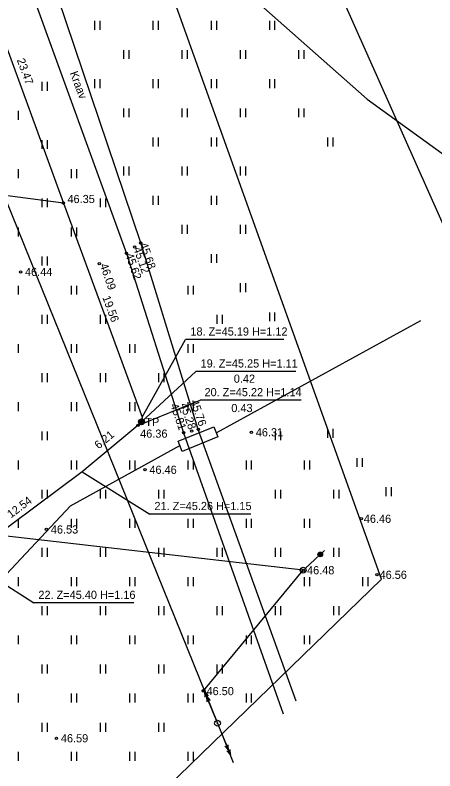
# Model space of a CAD drawing. Extents: x 642747 to 644424, y 6457048 to 6458238.
# Drawn here: x 644107 to 644143, y 6457581.9 to 6457646.8 of the extents above; entities that cross this region are included whole.
import ezdxf

# ---------------------------------------------------------------- set-up
doc = ezdxf.new("R2010")
doc.units = 0
for name, color, linetype in [('HALJASTUS', 7, 'Continuous'), ('JOONSIDE', 7, 'Continuous'), ('KOORDPUNKT', 7, 'Continuous'), ('KORGUS', 7, 'Continuous'), ('KPKAABEL', 7, 'Continuous'), ('KPOHULIIN', 7, 'Continuous'), ('MOOTPIIR', 7, 'Continuous'), ('PIIR', 7, 'Continuous'), ('POST', 7, 'Continuous'), ('RAJATIS', 7, 'Continuous'), ('SIOHULIIN', 7, 'Continuous'), ('SITRASS', 7, 'Continuous'), ('TEE', 7, 'Continuous'), ('VEEKOGU', 7, 'Continuous'), ('VORMISTUS', 7, 'Continuous')]:
    doc.layers.add(name, color=color, linetype=linetype)

msp = doc.modelspace()

# ---------------------------------------------------------------- linework, layer by layer
at = {"layer": 'HALJASTUS'}
for p, q in [((644113.79, 6457646.289), (644113.79, 6457645.528)), ((644114.245, 6457646.289), (644114.245, 6457645.528)), ((644118.79, 6457646.289), (644118.79, 6457645.528)), ((644119.245, 6457646.289), (644119.245, 6457645.528)), ((644123.79, 6457646.289), (644123.79, 6457645.528)), ((644124.245, 6457646.289), (644124.245, 6457645.528)), ((644128.79, 6457646.289), (644128.79, 6457645.528)), ((644129.245, 6457646.289), (644129.245, 6457645.528)), ((644116.29, 6457643.789), (644116.29, 6457643.028)), ((644116.745, 6457643.789), (644116.745, 6457643.028)), ((644121.29, 6457643.789), (644121.29, 6457643.028)), ((644121.745, 6457643.789), (644121.745, 6457643.028)), ((644126.29, 6457643.789), (644126.29, 6457643.028)), ((644126.745, 6457643.789), (644126.745, 6457643.028)), ((644131.29, 6457643.789), (644131.29, 6457643.028)), ((644131.745, 6457643.789), (644131.745, 6457643.028)), ((644113.79, 6457641.289), (644113.79, 6457640.528)), ((644114.245, 6457641.289), (644114.245, 6457640.528)), ((644118.79, 6457641.289), (644118.79, 6457640.528)), ((644119.245, 6457641.289), (644119.245, 6457640.528)), ((644123.79, 6457641.289), (644123.79, 6457640.528)), ((644124.245, 6457641.289), (644124.245, 6457640.528)), ((644128.79, 6457641.289), (644128.79, 6457640.528)), ((644129.245, 6457641.289), (644129.245, 6457640.528)), ((644109.29, 6457641.069), (644109.29, 6457640.307)), ((644109.745, 6457641.069), (644109.745, 6457640.307)), ((644116.29, 6457638.789), (644116.29, 6457638.028)), ((644116.745, 6457638.789), (644116.745, 6457638.028)), ((644121.29, 6457638.789), (644121.29, 6457638.028)), ((644121.745, 6457638.789), (644121.745, 6457638.028)), ((644126.29, 6457638.789), (644126.29, 6457638.028)), ((644126.745, 6457638.789), (644126.745, 6457638.028)), ((644131.29, 6457638.789), (644131.29, 6457638.028)), ((644131.745, 6457638.789), (644131.745, 6457638.028)), ((644107.245, 6457638.569), (644107.245, 6457637.807)), ((644109.29, 6457636.069), (644109.29, 6457635.307)), ((644109.745, 6457636.069), (644109.745, 6457635.307)), ((644118.79, 6457636.289), (644118.79, 6457635.528)), ((644119.245, 6457636.289), (644119.245, 6457635.528)), ((644123.79, 6457636.289), (644123.79, 6457635.528)), ((644124.245, 6457636.289), (644124.245, 6457635.528)), ((644133.79, 6457636.289), (644133.79, 6457635.528)), ((644134.245, 6457636.289), (644134.245, 6457635.528)), ((644107.245, 6457633.569), (644107.245, 6457632.807)), ((644111.79, 6457633.569), (644111.79, 6457632.807)), ((644112.245, 6457633.569), (644112.245, 6457632.807)), ((644116.29, 6457633.789), (644116.29, 6457633.028)), ((644116.745, 6457633.789), (644116.745, 6457633.028)), ((644121.29, 6457633.789), (644121.29, 6457633.028)), ((644121.745, 6457633.789), (644121.745, 6457633.028)), ((644126.29, 6457633.789), (644126.29, 6457633.028)), ((644126.745, 6457633.789), (644126.745, 6457633.028)), ((644109.29, 6457631.069), (644109.29, 6457630.307)), ((644109.745, 6457631.069), (644109.745, 6457630.307)), ((644114.29, 6457631.069), (644114.29, 6457630.307)), ((644114.745, 6457631.069), (644114.745, 6457630.307)), ((644118.79, 6457631.289), (644118.79, 6457630.528)), ((644119.245, 6457631.289), (644119.245, 6457630.528)), ((644123.79, 6457631.289), (644123.79, 6457630.528)), ((644124.245, 6457631.289), (644124.245, 6457630.528)), ((644107.245, 6457628.569), (644107.245, 6457627.807)), ((644111.79, 6457628.569), (644111.79, 6457627.807)), ((644112.245, 6457628.569), (644112.245, 6457627.807)), ((644121.29, 6457628.789), (644121.29, 6457628.028)), ((644121.745, 6457628.789), (644121.745, 6457628.028)), ((644126.29, 6457628.789), (644126.29, 6457628.028)), ((644126.745, 6457628.789), (644126.745, 6457628.028)), ((644123.79, 6457626.289), (644123.79, 6457625.528)), ((644124.245, 6457626.289), (644124.245, 6457625.528)), ((644109.29, 6457626.069), (644109.29, 6457625.307)), ((644109.745, 6457626.069), (644109.745, 6457625.307)), ((644126.29, 6457623.789), (644126.29, 6457623.028)), ((644126.745, 6457623.789), (644126.745, 6457623.028)), ((644107.245, 6457623.569), (644107.245, 6457622.807)), ((644111.79, 6457623.569), (644111.79, 6457622.807)), ((644112.245, 6457623.569), (644112.245, 6457622.807)), ((644121.79, 6457623.569), (644121.79, 6457622.807)), ((644122.245, 6457623.569), (644122.245, 6457622.807)), ((644109.29, 6457621.069), (644109.29, 6457620.307)), ((644109.745, 6457621.069), (644109.745, 6457620.307)), ((644114.29, 6457621.069), (644114.29, 6457620.307)), ((644114.745, 6457621.069), (644114.745, 6457620.307)), ((644124.29, 6457621.069), (644124.29, 6457620.307)), ((644124.745, 6457621.069), (644124.745, 6457620.307)), ((644128.79, 6457621.289), (644128.79, 6457620.528)), ((644129.245, 6457621.289), (644129.245, 6457620.528)), ((644107.245, 6457618.569), (644107.245, 6457617.807)), ((644111.79, 6457618.569), (644111.79, 6457617.807)), ((644112.245, 6457618.569), (644112.245, 6457617.807)), ((644116.79, 6457618.569), (644116.79, 6457617.807)), ((644117.245, 6457618.569), (644117.245, 6457617.807)), ((644121.79, 6457618.569), (644121.79, 6457617.807)), ((644122.245, 6457618.569), (644122.245, 6457617.807)), ((644109.29, 6457616.069), (644109.29, 6457615.307)), ((644109.745, 6457616.069), (644109.745, 6457615.307)), ((644114.29, 6457616.069), (644114.29, 6457615.307)), ((644114.745, 6457616.069), (644114.745, 6457615.307)), ((644119.29, 6457616.069), (644119.29, 6457615.307)), ((644119.745, 6457616.069), (644119.745, 6457615.307)), ((644107.245, 6457613.569), (644107.245, 6457612.807)), ((644111.79, 6457613.569), (644111.79, 6457612.807)), ((644112.245, 6457613.569), (644112.245, 6457612.807)), ((644116.79, 6457613.569), (644116.79, 6457612.807)), ((644117.245, 6457613.569), (644117.245, 6457612.807)), ((644121.79, 6457613.569), (644121.79, 6457612.807)), ((644122.245, 6457613.569), (644122.245, 6457612.807)), ((644109.29, 6457611.069), (644109.29, 6457610.307)), ((644109.745, 6457611.069), (644109.745, 6457610.307)), ((644129.29, 6457611.069), (644129.29, 6457610.307)), ((644129.745, 6457611.069), (644129.745, 6457610.307)), ((644133.79, 6457611.289), (644133.79, 6457610.528)), ((644134.245, 6457611.289), (644134.245, 6457610.528)), ((644136.29, 6457608.789), (644136.29, 6457608.028)), ((644136.745, 6457608.789), (644136.745, 6457608.028)), ((644107.245, 6457608.569), (644107.245, 6457607.807)), ((644111.79, 6457608.569), (644111.79, 6457607.807)), ((644112.245, 6457608.569), (644112.245, 6457607.807)), ((644116.79, 6457608.569), (644116.79, 6457607.807)), ((644117.245, 6457608.569), (644117.245, 6457607.807)), ((644121.79, 6457608.569), (644121.79, 6457607.807)), ((644122.245, 6457608.569), (644122.245, 6457607.807)), ((644126.79, 6457608.569), (644126.79, 6457607.807)), ((644127.245, 6457608.569), (644127.245, 6457607.807)), ((644131.79, 6457608.569), (644131.79, 6457607.807)), ((644132.245, 6457608.569), (644132.245, 6457607.807)), ((644138.79, 6457606.289), (644138.79, 6457605.528)), ((644139.245, 6457606.289), (644139.245, 6457605.528)), ((644109.29, 6457606.069), (644109.29, 6457605.307)), ((644109.745, 6457606.069), (644109.745, 6457605.307)), ((644114.29, 6457606.069), (644114.29, 6457605.307)), ((644114.745, 6457606.069), (644114.745, 6457605.307)), ((644119.29, 6457606.069), (644119.29, 6457605.307)), ((644119.745, 6457606.069), (644119.745, 6457605.307)), ((644129.29, 6457606.069), (644129.29, 6457605.307)), ((644129.745, 6457606.069), (644129.745, 6457605.307)), ((644134.29, 6457606.069), (644134.29, 6457605.307)), ((644134.745, 6457606.069), (644134.745, 6457605.307)), ((644107.245, 6457603.569), (644107.245, 6457602.807)), ((644111.79, 6457603.569), (644111.79, 6457602.807)), ((644112.245, 6457603.569), (644112.245, 6457602.807)), ((644116.79, 6457603.569), (644116.79, 6457602.807)), ((644117.245, 6457603.569), (644117.245, 6457602.807)), ((644121.79, 6457603.569), (644121.79, 6457602.807)), ((644122.245, 6457603.569), (644122.245, 6457602.807)), ((644126.79, 6457603.569), (644126.79, 6457602.807)), ((644127.245, 6457603.569), (644127.245, 6457602.807)), ((644131.79, 6457603.569), (644131.79, 6457602.807)), ((644132.245, 6457603.569), (644132.245, 6457602.807)), ((644109.29, 6457601.069), (644109.29, 6457600.307)), ((644109.745, 6457601.069), (644109.745, 6457600.307)), ((644114.29, 6457601.069), (644114.29, 6457600.307)), ((644114.745, 6457601.069), (644114.745, 6457600.307)), ((644119.29, 6457601.069), (644119.29, 6457600.307)), ((644119.745, 6457601.069), (644119.745, 6457600.307)), ((644124.29, 6457601.069), (644124.29, 6457600.307)), ((644124.745, 6457601.069), (644124.745, 6457600.307)), ((644129.29, 6457601.069), (644129.29, 6457600.307)), ((644129.745, 6457601.069), (644129.745, 6457600.307)), ((644134.29, 6457601.069), (644134.29, 6457600.307)), ((644134.745, 6457601.069), (644134.745, 6457600.307)), ((644107.245, 6457598.569), (644107.245, 6457597.807)), ((644111.79, 6457598.569), (644111.79, 6457597.807)), ((644112.245, 6457598.569), (644112.245, 6457597.807)), ((644116.79, 6457598.569), (644116.79, 6457597.807)), ((644117.245, 6457598.569), (644117.245, 6457597.807)), ((644121.79, 6457598.569), (644121.79, 6457597.807)), ((644122.245, 6457598.569), (644122.245, 6457597.807)), ((644131.79, 6457598.569), (644131.79, 6457597.807)), ((644132.245, 6457598.569), (644132.245, 6457597.807)), ((644136.79, 6457598.569), (644136.79, 6457597.807)), ((644137.245, 6457598.569), (644137.245, 6457597.807)), ((644109.29, 6457596.069), (644109.29, 6457595.307)), ((644109.745, 6457596.069), (644109.745, 6457595.307)), ((644114.29, 6457596.069), (644114.29, 6457595.307)), ((644114.745, 6457596.069), (644114.745, 6457595.307)), ((644119.29, 6457596.069), (644119.29, 6457595.307)), ((644119.745, 6457596.069), (644119.745, 6457595.307)), ((644124.29, 6457596.069), (644124.29, 6457595.307)), ((644124.745, 6457596.069), (644124.745, 6457595.307)), ((644129.29, 6457596.069), (644129.29, 6457595.307)), ((644129.745, 6457596.069), (644129.745, 6457595.307)), ((644134.29, 6457596.069), (644134.29, 6457595.307)), ((644134.745, 6457596.069), (644134.745, 6457595.307)), ((644107.245, 6457593.569), (644107.245, 6457592.807)), ((644111.79, 6457593.569), (644111.79, 6457592.807)), ((644112.245, 6457593.569), (644112.245, 6457592.807)), ((644116.79, 6457593.569), (644116.79, 6457592.807)), ((644117.245, 6457593.569), (644117.245, 6457592.807)), ((644121.79, 6457593.569), (644121.79, 6457592.807)), ((644122.245, 6457593.569), (644122.245, 6457592.807)), ((644126.79, 6457593.569), (644126.79, 6457592.807)), ((644127.245, 6457593.569), (644127.245, 6457592.807)), ((644131.79, 6457593.569), (644131.79, 6457592.807)), ((644132.245, 6457593.569), (644132.245, 6457592.807)), ((644109.29, 6457591.069), (644109.29, 6457590.307)), ((644109.745, 6457591.069), (644109.745, 6457590.307)), ((644114.29, 6457591.069), (644114.29, 6457590.307)), ((644114.745, 6457591.069), (644114.745, 6457590.307)), ((644119.29, 6457591.069), (644119.29, 6457590.307)), ((644119.745, 6457591.069), (644119.745, 6457590.307)), ((644124.29, 6457591.069), (644124.29, 6457590.307)), ((644124.745, 6457591.069), (644124.745, 6457590.307)), ((644107.245, 6457588.569), (644107.245, 6457587.807)), ((644111.79, 6457588.569), (644111.79, 6457587.807)), ((644112.245, 6457588.569), (644112.245, 6457587.807)), ((644116.79, 6457588.569), (644116.79, 6457587.807)), ((644117.245, 6457588.569), (644117.245, 6457587.807)), ((644121.79, 6457588.569), (644121.79, 6457587.807)), ((644122.245, 6457588.569), (644122.245, 6457587.807)), ((644126.79, 6457588.569), (644126.79, 6457587.807)), ((644127.245, 6457588.569), (644127.245, 6457587.807)), ((644109.29, 6457586.069), (644109.29, 6457585.307)), ((644109.745, 6457586.069), (644109.745, 6457585.307)), ((644114.29, 6457586.069), (644114.29, 6457585.307)), ((644114.745, 6457586.069), (644114.745, 6457585.307)), ((644119.29, 6457586.069), (644119.29, 6457585.307)), ((644119.745, 6457586.069), (644119.745, 6457585.307)), ((644107.245, 6457583.569), (644107.245, 6457582.807)), ((644111.79, 6457583.569), (644111.79, 6457582.807)), ((644112.245, 6457583.569), (644112.245, 6457582.807)), ((644116.79, 6457583.569), (644116.79, 6457582.807)), ((644117.245, 6457583.569), (644117.245, 6457582.807)), ((644121.79, 6457583.569), (644121.79, 6457582.807)), ((644122.245, 6457583.569), (644122.245, 6457582.807))]:
    msp.add_line(p, q, dxfattribs=at)
at = {"layer": 'KOORDPUNKT'}
for p, q in [((644111.131, 6457630.665), (644103.648, 6457631.648)), ((644117.872, 6457612.305), (644121.601, 6457618.945)), ((644130.035, 6457618.945), (644121.601, 6457618.945)), ((644117.831, 6457611.89), (644122.476, 6457616.205)), ((644131.05, 6457616.205), (644122.476, 6457616.205)), ((644117.527, 6457611.592), (644122.846, 6457613.74)), ((644131.525, 6457613.74), (644122.846, 6457613.74)), ((644112.751, 6457607.616), (644118.554, 6457603.972)), ((644127.198, 6457603.972), (644118.554, 6457603.972)), ((644102.693, 6457600.124), (644108.602, 6457596.351)), ((644117.176, 6457596.351), (644108.602, 6457596.351))]:
    msp.add_line(p, q, dxfattribs=at)
for points in [[(644111.131, 6457630.665), (644111.131, 6457630.665), (644111.131, 6457630.665)], [(644117.872, 6457612.305), (644117.872, 6457612.305), (644117.872, 6457612.305)], [(644117.527, 6457611.592), (644117.527, 6457611.592), (644117.527, 6457611.592)], [(644117.831, 6457611.89), (644117.831, 6457611.89), (644117.831, 6457611.89)], [(644112.751, 6457607.616), (644112.751, 6457607.616), (644112.751, 6457607.616)]]:
    msp.add_lwpolyline(points, dxfattribs=at)
at = {"layer": 'KORGUS'}
for centre in [(644111.131, 6457630.665), (644117.232, 6457626.884), (644117.767, 6457627.249), (644116.541, 6457626.349), (644114.202, 6457625.466), (644107.462, 6457624.758), (644117.527, 6457611.592), (644122.69, 6457611.242), (644121.438, 6457610.958), (644122.126, 6457611.098), (644127.254, 6457610.998), (644118.129, 6457607.782), (644136.669, 6457603.577), (644109.681, 6457602.658), (644131.692, 6457599.165), (644138.019, 6457598.77), (644110.539, 6457584.742)]:
    msp.add_circle(centre, 0.1, dxfattribs=at)
at = {"layer": 'KPKAABEL'}
msp.add_lwpolyline([(644103.079, 6457652.715), (644111.131, 6457630.665), (644117.872, 6457612.305), (644117.831, 6457611.89), (644117.527, 6457611.592), (644112.751, 6457607.616), (644102.693, 6457600.124), (644092.698, 6457590.582), (644078.192, 6457577.561), (644066.524, 6457567.369), (644056.896, 6457559.139), (644048.865, 6457552.537), (644048.039, 6457551.927), (644047.155, 6457551.979), (644039.639, 6457557.844), (644029.553, 6457566.384), (644016.901, 6457577.396), (644002.145, 6457590.823), (643989.718, 6457602.415), (643976.894, 6457615.305), (643965.556, 6457626.702)], dxfattribs=at)
at = {"layer": 'KPOHULIIN'}
for p, q in [((644123.238, 6457588.754), (644123.269, 6457588.279)), ((644123.238, 6457588.754), (644123.546, 6457588.391)), ((644124.248, 6457586.263), (644123.238, 6457588.754)), ((644123.403, 6457588.348), (644123.71, 6457587.985)), ((644123.403, 6457588.348), (644123.433, 6457587.873)), ((644124.436, 6457585.8), (644125.452, 6457583.311)), ((644125.286, 6457583.716), (644125.255, 6457584.191)), ((644125.286, 6457583.716), (644124.978, 6457584.078)), ((644125.452, 6457583.311), (644125.143, 6457583.673)), ((644125.452, 6457583.311), (644125.42, 6457583.785))]:
    msp.add_line(p, q, dxfattribs=at)
msp.add_lwpolyline([(644061.981, 6457739.913), (644094.239, 6457660.452), (644124.342, 6457586.031), (644125.691, 6457582.672)], dxfattribs=at)
at = {"layer": 'MOOTPIIR'}
msp.add_lwpolyline([(643525.446, 6457467.559), (643537.447, 6457435.458), (643944.848, 6457628.51), (644046.626, 6457529.09), (644067.022, 6457529.09), (644138.408, 6457598.401), (644075.1, 6457775.215), (644046.02, 6457752.582), (644092.466, 6457611.94), (644070.657, 6457576.375), (644041.981, 6457570.717), (643942.223, 6457662.862)], close=True, dxfattribs=at)
at = {"layer": 'PIIR'}
msp.add_lwpolyline([(644119.21, 6457655.5), (644137.18, 6457639.57), (644176.94, 6457610.8), (644193.44, 6457599.42), (644220.94, 6457583.42), (644258.83, 6457557.54), (644299.64, 6457526.51), (644330.13, 6457505.12), (644351.66, 6457500.83), (644373.13, 6457501.25), (644368.81, 6457508.24), (644366.6, 6457513.63), (644352.78, 6457513.35), (644335.16, 6457516.88), (644304.29, 6457538.7), (644233.94, 6457592.97), (644213.34, 6457605.08), (644212.32, 6457605.7), (644192.23, 6457620.22), (644172.44, 6457634.51), (644128.57, 6457664.58)], dxfattribs=at)
at = {"layer": 'POST'}
msp.add_lwpolyline([(644123.155, 6457588.814), (644131.692, 6457599.165)], dxfattribs=at)
for centre, radius in [((644117.831, 6457611.89), 0.25), ((644117.831, 6457611.89), 0.225), ((644117.831, 6457611.89), 0.2), ((644117.831, 6457611.89), 0.175), ((644117.831, 6457611.89), 0.15), ((644117.831, 6457611.89), 0.125), ((644117.831, 6457611.89), 0.1), ((644117.831, 6457611.89), 0.075), ((644117.831, 6457611.89), 0.05), ((644117.831, 6457611.89), 0.025), ((644131.692, 6457599.165), 0.25), ((644123.155, 6457588.814), 0.125), ((644123.155, 6457588.814), 0.105), ((644123.155, 6457588.814), 0.0851), ((644123.155, 6457588.814), 0.0651), ((644123.155, 6457588.814), 0.0451), ((644123.155, 6457588.814), 0.0251), ((644123.155, 6457588.814), 0.00511), ((644124.342, 6457586.031), 0.25), ((644124.342, 6457586.031), 0.0234)]:
    msp.add_circle(centre, radius, dxfattribs=at)
at = {"layer": 'RAJATIS'}
msp.add_lwpolyline([(644120.964, 6457610.223), (644124.038, 6457611.478), (644124.386, 6457610.603), (644121.302, 6457609.359), (644120.964, 6457610.223)], dxfattribs=at)
at = {"layer": 'SIOHULIIN'}
msp.add_line((644131.876, 6457599.334), (644133.523, 6457600.853), dxfattribs=at)
for radius in [0.199, 0.19, 0.18, 0.171, 0.162, 0.152, 0.143, 0.133, 0.124, 0.114, 0.105, 0.0953, 0.0858, 0.0763, 0.0669, 0.0574, 0.0479, 0.0385, 0.029, 0.0195, 0.0101, 0.00061]:
    msp.add_circle((644133.158, 6457600.517), radius, dxfattribs=at)
at = {"layer": 'SITRASS'}
msp.add_lwpolyline([(644131.692, 6457599.165), (644103.261, 6457602.416), (644090.598, 6457603.655)], dxfattribs=at)
at = {"layer": 'TEE'}
for points in [[(644124.276, 6457610.977), (644141.767, 6457620.6)], [(644051.619, 6457549.694), (644075.076, 6457569.399), (644100.273, 6457592.468), (644111.741, 6457604.69), (644121.185, 6457609.883)]]:
    msp.add_lwpolyline(points, dxfattribs=at)
at = {"layer": 'VEEKOGU'}
for points in [[(644131.098, 6457587.913), (644122.69, 6457611.242), (644117.767, 6457627.249), (644109.969, 6457650.392)], [(644108.124, 6457649.581), (644116.541, 6457626.349), (644121.438, 6457610.958), (644129.984, 6457586.833)]]:
    msp.add_lwpolyline(points, dxfattribs=at)
at = {"layer": 'VORMISTUS'}
msp.add_line((644034.968, 6457873.554), (644180.435, 6457546.05), dxfattribs=at)

# ---------------------------------------------------------------- texts
at = {"layer": 'JOONSIDE'}
for s, rotation, p in [('23.47', 290.06068, (644107.125, 6457642.946)), ('19.56', 290.16106, (644114.46, 6457622.576)), ('6.21', 39.77724, (644114.156, 6457609.516)), ('12.54', 36.68168, (644106.629, 6457603.598))]:
    msp.add_text(s, height=0.7, rotation=rotation, dxfattribs=at).set_placement(p)
for s, p in [('0.42', (644125.741, 6457615.249)), ('0.43', (644125.531, 6457612.73))]:
    msp.add_text(s, height=0.7, dxfattribs=at).set_placement(p)
at = {"layer": 'KOORDPUNKT'}
for s, p in [('18. Z=45.19 H=1.12', (644122.021, 6457619.295)), ('19. Z=45.25 H=1.11', (644122.896, 6457616.555)), ('20. Z=45.22 H=1.14', (644123.231, 6457614.09)), ('21. Z=45.26 H=1.15', (644118.939, 6457604.322)), ('22. Z=45.40 H=1.16', (644108.987, 6457596.701))]:
    msp.add_text(s, height=0.7, dxfattribs=at).set_placement(p)
at = {"layer": 'KORGUS'}
for s, p in [('46.35', (644111.481, 6457630.665)), ('46.44', (644107.837, 6457624.408)), ('46.31', (644127.629, 6457610.648)), ('46.36', (644117.712, 6457610.533)), ('46.46', (644118.504, 6457607.432)), ('46.46', (644136.89, 6457603.227)), ('46.53', (644110.056, 6457602.308)), ('46.48', (644132.022, 6457598.815)), ('46.56', (644138.24, 6457598.42)), ('46.50', (644123.404, 6457588.442)), ('46.59', (644110.914, 6457584.392))]:
    msp.add_text(s, height=0.7, dxfattribs=at).set_placement(p)
for s, p in [('45.68', (644117.658, 6457627.135)), ('45.62', (644116.432, 6457626.235)), ('45.12', (644117.123, 6457626.77)), ('46.09', (644114.246, 6457625.352)), ('45.81', (644120.281, 6457613.338)), ('45.28', (644121.12, 6457613.384)), ('45.76', (644122.006, 6457613.664))]:
    msp.add_text(s, height=0.7, rotation=289.05228, dxfattribs=at).set_placement(p)
at = {"layer": 'POST'}
msp.add_text('TP', height=0.7, dxfattribs=at).set_placement((644118.157, 6457611.537))
at = {"layer": 'VEEKOGU'}
msp.add_text('Kraav', height=0.7, rotation=290.71023, dxfattribs=at).set_placement((644111.67, 6457641.825))

doc.saveas('drawing.dxf')
